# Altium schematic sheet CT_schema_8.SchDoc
size 278 x 170 mm
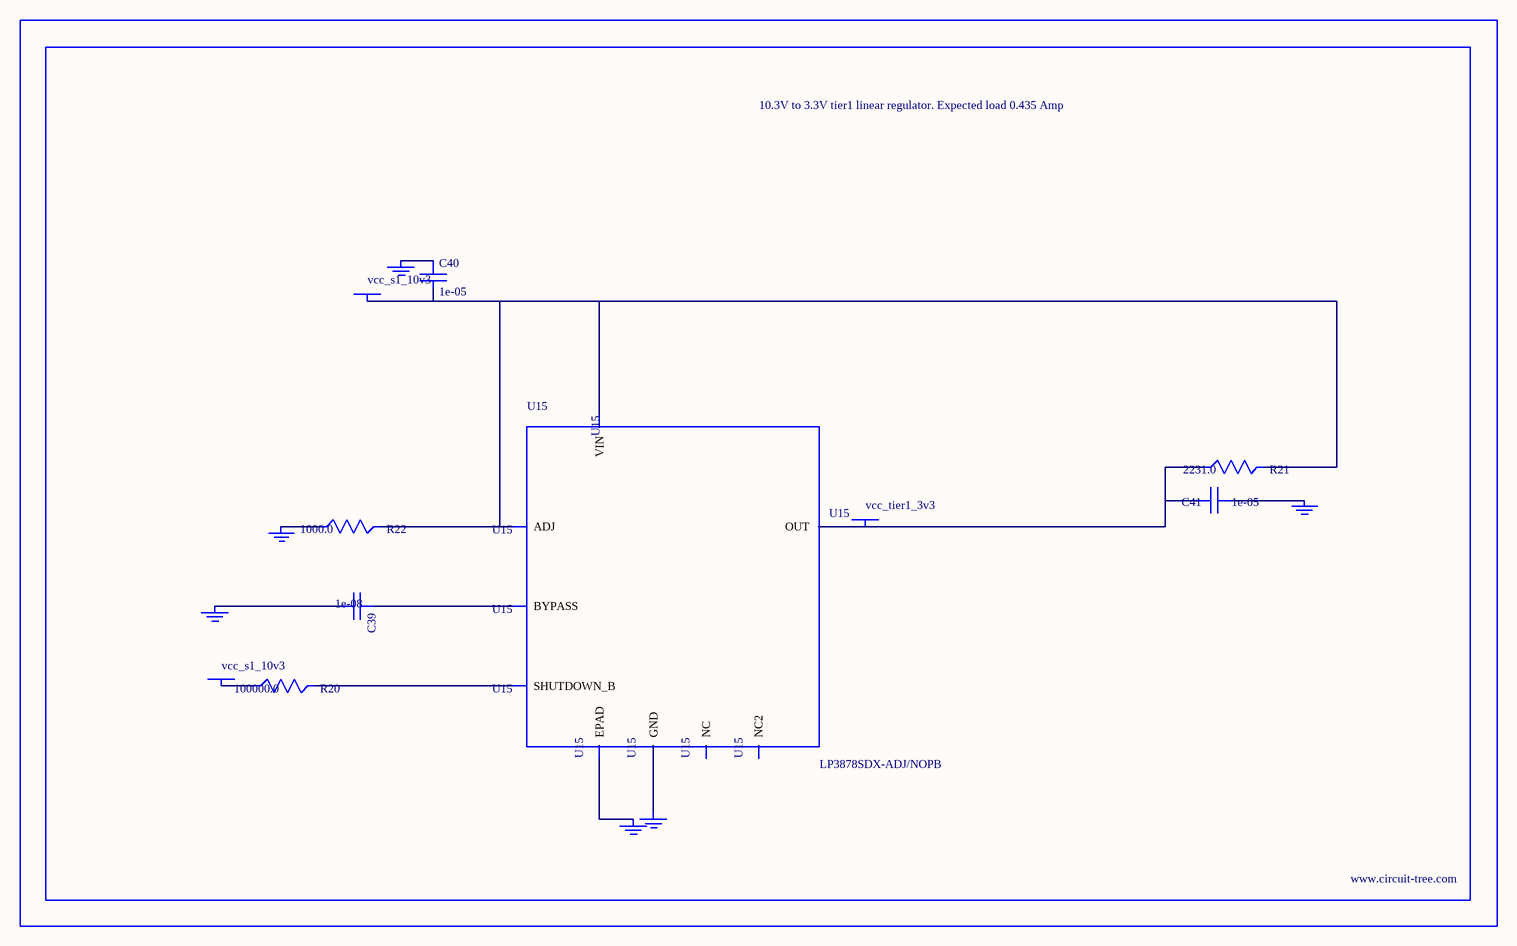
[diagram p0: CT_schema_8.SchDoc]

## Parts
BORDER7  (no value)
C39  1e-08  [C0402]
C40  1e-05  [C1206]
C41  1e-05  [C1210]
GND_INSTANCE_7_0  (no value)
GND_INSTANCE_7_1  (no value)
GND_INSTANCE_7_2  (no value)
GND_INSTANCE_7_3  (no value)
GND_INSTANCE_7_4  (no value)
GND_INSTANCE_7_5  (no value)
POWER_INSTANCE_7_0  vcc_s1_10v3
POWER_INSTANCE_7_1  vcc_s1_10v3
POWER_INSTANCE_7_2  vcc_tier1_3v3
R20  100000.0  [R0603]
R21  2231.0  [R0603]
R22  1000.0  [R0603]
U15  LP3878SDX-ADJ/NOPB  [WSON-8]

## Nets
NetC39_1: C39.1 U15.1(BYPASS)
NetC39_2: C39.2 GND_INSTANCE_7_0.0(GND)
NetC40_1: C40.1 GND_INSTANCE_7_1.0(GND)
NetC40_2: C40.2 POWER_INSTANCE_7_0.0(PWR) R21.2 R22.2 U15.4(VIN) U15.6(ADJ)
NetC41_1: C41.1 GND_INSTANCE_7_2.0(GND)
NetC41_2: C41.2 POWER_INSTANCE_7_2.0(PWR) R21.1 U15.5(OUT)
NetGND_INSTANCE_7_3_0: GND_INSTANCE_7_3.0(GND) R22.1
NetGND_INSTANCE_7_4_0: GND_INSTANCE_7_4.0(GND) U15.PAD(EPAD)
NetGND_INSTANCE_7_5_0: GND_INSTANCE_7_5.0(GND) U15.3(GND)
NetPOWER_INSTANCE_7_1_0: POWER_INSTANCE_7_1.0(PWR) R20.1
NetR20_2: R20.2 U15.8(SHUTDOWN_B)

Not connected (* = marked no-connect by the designer): U15 2(NC) 7(NC2)

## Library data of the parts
BORDER7 = BORDER_PAGE7
C39 = C0402C103K3RAC
C40 = C1206C106K3RACTU
C41 = GRM32DR61E106MA12L
GND_INSTANCE_7_0-GND_INSTANCE_7_5 = GND
POWER_INSTANCE_7_0-POWER_INSTANCE_7_2 = PWR
R20 = RC0603JR-07100KL
R21 = R21
R22 = RC0603JR-071KL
